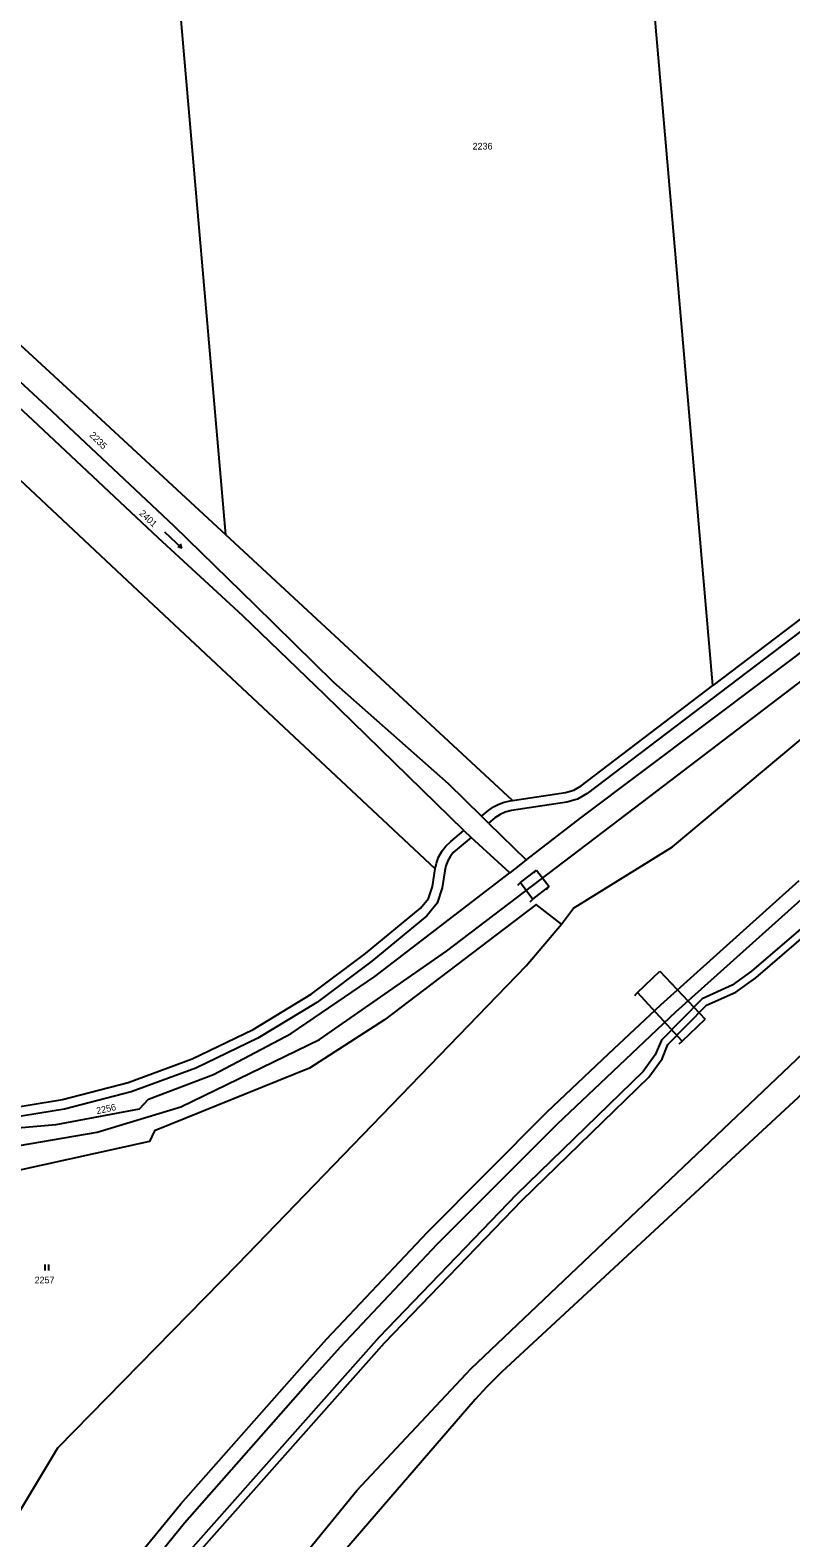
# Model space of a CAD drawing. Extents: x -504988 to -494607, y -1123820 to -1114018.
# Drawn here: x -499040.2 to -498846.7, y -1121962.3 to -1121578.3 of the extents above; entities that cross this region are included whole.
import ezdxf

# ---------------------------------------------------------------- set-up
doc = ezdxf.new("R2010")
doc.units = 0
for name, color, linetype in [('Hranice parcel', 7, 'Continuous'), ('Parcelní čísla', 7, 'Continuous'), ('Poz předměty', 7, 'Continuous'), ('Vnitřní kresba', 7, 'Continuous'), ('Věcná břemena k části', 7, 'Continuous'), ('Značky kultur', 7, 'Continuous')]:
    doc.layers.add(name, color=color, linetype=linetype)

msp = doc.modelspace()

# ---------------------------------------------------------------- linework, layer by layer
at = {"layer": 'Hranice parcel'}
for p, q in [((-498917.52, -1121774.47), (-498990.43, -1121706.85)), ((-498923.58, -1121780.26), (-498925.38, -1121778.5)), ((-498923.58, -1121780.26), (-498914, -1121789.64)), ((-498929.86, -1121782.17), (-498927.99, -1121783.94)), ((-498918.2, -1121792.88), (-498927.99, -1121783.94))]:
    msp.add_line(p, q, dxfattribs=at)
for points in [[(-498866.47, -1121745.24), (-498879.54, -1121594.25), (-498892.61, -1121443.25)], [(-498990.43, -1121706.85), (-499001.1, -1121583.62), (-499011.76, -1121460.39)], [(-498538.01, -1121477.88), (-498569.56, -1121529.32), (-498579.83, -1121544.03), (-498591.77, -1121557.42), (-498605.21, -1121569.3), (-498619.96, -1121579.5), (-498732.29, -1121647.73), (-498740.98, -1121653.33), (-498749.37, -1121659.37), (-498898.52, -1121772.74), (-498900.95, -1121774.14), (-498903.65, -1121774.9), (-498917.72, -1121777.03), (-498919.32, -1121777.43), (-498920.66, -1121778.04), (-498921.96, -1121778.92), (-498923.58, -1121780.26)], [(-498914, -1121789.64), (-498913.86, -1121789.53), (-498900.12, -1121778.95), (-498774.91, -1121684.77), (-498768.24, -1121679.75), (-498738.52, -1121657.4), (-498715.59, -1121643.62), (-498682.52, -1121624.8), (-498650.6, -1121606.88), (-498629.68, -1121595.09), (-498598.09, -1121571.17), (-498579, -1121548.45), (-498555.72, -1121510.08), (-498538.84, -1121481), (-498537.25, -1121478.26)], [(-498905.05, -1121806.02), (-498901.99, -1121801.93), (-498876.77, -1121786.32), (-498775.84, -1121701.77), (-498740.86, -1121675.73), (-498709.59, -1121654.46), (-498671.28, -1121630.46), (-498564.1, -1121580.75), (-498495.09, -1121548.95), (-498498.9, -1121529.72), (-498500.1, -1121523.64), (-498505.78, -1121492.74)], [(-498555.23, -1121501.17), (-498571.7, -1121528.02), (-498581.8, -1121542.48), (-498593.54, -1121555.65), (-498606.75, -1121567.33), (-498621.26, -1121577.37), (-498733.59, -1121645.6), (-498742.39, -1121651.26), (-498750.89, -1121657.38), (-498866.47, -1121745.24)], [(-499000.48, -1122008.5), (-498998.46, -1122000.92), (-498957.1, -1121950.18), (-498928.11, -1121919.18), (-498841.81, -1121837.2), (-498840.75, -1121836.19), (-498837.47, -1121833.23), (-498757.15, -1121760.88), (-498721.23, -1121733.16), (-498721.69, -1121739.51), (-498654.67, -1121691.99), (-498621.86, -1121665.7), (-498610.05, -1121656.24), (-498572.09, -1121630.11), (-498534.03, -1121605.63), (-498489.21, -1121578.24), (-498451.03, -1121555.26), (-498445.93, -1121552.19), (-498412.54, -1121539.26)], [(-499149.08, -1121616.48), (-499136.35, -1121616.98), (-499129.71, -1121616.1), (-499117.81, -1121617.5), (-499096.78, -1121624.2), (-499073.93, -1121639.14), (-499036.06, -1121674.08), (-499003.69, -1121704.58), (-498983.09, -1121724.69), (-498963.04, -1121744.39), (-498933.88, -1121770.18), (-498925.38, -1121778.5)], [(-498929.86, -1121782.17), (-498965.23, -1121747.63), (-498986.15, -1121727.51), (-499007.63, -1121707.59), (-499039.56, -1121677.69), (-499073.7, -1121646), (-499094.22, -1121630.8), (-499111.67, -1121623.38), (-499128.27, -1121620.51), (-499144.04, -1121623.98), (-499151.52, -1121625.62)], [(-498937.2, -1121791.9), (-499014.09, -1121719.86), (-499090.98, -1121647.81), (-499104.22, -1121639.12), (-499120.52, -1121633.88), (-499135.44, -1121634.17), (-499155.01, -1121639.17)], [(-499058, -1121644.5), (-499023.32, -1121676.35), (-498990.43, -1121706.85)], [(-498917.52, -1121774.47), (-498904.02, -1121772.43), (-498901.92, -1121771.84), (-498900.03, -1121770.75), (-498866.47, -1121745.24)], [(-498925.38, -1121778.5), (-498923.55, -1121776.99), (-498922.29, -1121776.09), (-498920.98, -1121775.4), (-498919.57, -1121774.89), (-498918.09, -1121774.56), (-498917.52, -1121774.47)], [(-498927.99, -1121783.94), (-498932.56, -1121787.75), (-498933.39, -1121788.82), (-498933.98, -1121789.86), (-498934.47, -1121791.14), (-498934.74, -1121792.4), (-498935.36, -1121796.74), (-498936.68, -1121800.66), (-498939.32, -1121803.84), (-498953.28, -1121815.39), (-498967.31, -1121825.9), (-498982.28, -1121835), (-498998.06, -1121842.62), (-499014.51, -1121848.67), (-499031.47, -1121853.11), (-499048.77, -1121855.9), (-499066.26, -1121856.99), (-499083.78, -1121856.4), (-499101.15, -1121854.11), (-499118.23, -1121850.16), (-499144.81, -1121842.63)], [(-498937.2, -1121791.9), (-498936.86, -1121790.42), (-498936.29, -1121788.91), (-498935.42, -1121787.36), (-498934.44, -1121786.09), (-498933.22, -1121784.93), (-498929.86, -1121782.17)], [(-499049.05, -1121853.41), (-499031.98, -1121850.67), (-499015.26, -1121846.29), (-498999.04, -1121840.32), (-498983.47, -1121832.8), (-498968.71, -1121823.82), (-498954.87, -1121813.46), (-498940.92, -1121801.91), (-498938.86, -1121799.44), (-498937.83, -1121796.39), (-498937.2, -1121791.9)], [(-498914, -1121789.64), (-498915.79, -1121791.04), (-498918.2, -1121792.88)], [(-499144.81, -1121842.63), (-499143.52, -1121843.53), (-499139.17, -1121845.68), (-499106.35, -1121855.43), (-499080.4, -1121857.12), (-499078.61, -1121857.24), (-499079.46, -1121859.32), (-499067.94, -1121859.99), (-499033.65, -1121857.01), (-499012.44, -1121852.99), (-499010.15, -1121850.53), (-498993.59, -1121844.27), (-498973.79, -1121833.82), (-498952.54, -1121819.34), (-498918.2, -1121792.88)], [(-498905.05, -1121806.02), (-498911.48, -1121801.01), (-498950.02, -1121830.34), (-498969.17, -1121842.68), (-499008.55, -1121858.61), (-499009.88, -1121861.29), (-499044.06, -1121868.88), (-499063.78, -1121870.36), (-499085.95, -1121870.14), (-499097.79, -1121903.09)], [(-499047.42, -1121960.83), (-499045.12, -1121959.32), (-499033.21, -1121939.35), (-498987.34, -1121892.56), (-498914.04, -1121816.6), (-498905.05, -1121806.02)], [(-498831.03, -1121837.41), (-498920.32, -1121920.05), (-498924.06, -1121923.81), (-498926.95, -1121927.01), (-498990.74, -1122000.94), (-498992.65, -1122003.89), (-498993.35, -1122005.71)]]:
    msp.add_lwpolyline(points, dxfattribs=at)
at = {"layer": 'Poz předměty'}
for p, q in [((-498882.52, -1121773.46), (-498836.54, -1121738.36)), ((-498934.31, -1121812.86), (-498882.52, -1121773.46)), ((-498879.73, -1121826.51), (-498844.58, -1121794.87)), ((-498842.5, -1121798.35), (-498876.02, -1121828.36)), ((-498966.61, -1121835.4), (-498934.31, -1121812.86)), ((-498893.03, -1121839.04), (-498879.73, -1121826.51)), ((-498876.02, -1121828.36), (-498893.53, -1121845.07)), ((-499001.85, -1121852.52), (-498966.61, -1121835.4)), ((-498908.68, -1121853.76), (-498893.03, -1121839.04)), ((-498893.53, -1121845.07), (-498906.15, -1121856.88)), ((-499023.19, -1121858.99), (-499001.85, -1121852.52)), ((-498939.11, -1121884.44), (-498908.68, -1121853.76)), ((-498906.15, -1121856.88), (-498936.62, -1121887.44)), ((-499049.55, -1121863.51), (-499023.19, -1121858.99)), ((-498964.76, -1121911.58), (-498939.11, -1121884.44)), ((-498936.62, -1121887.44), (-498961.36, -1121913.74)), ((-498969.06, -1121916.4), (-498964.76, -1121911.58)), ((-498961.36, -1121913.74), (-498968.89, -1121922.11)), ((-499001.91, -1121953.56), (-498969.06, -1121916.4)), ((-498968.89, -1121922.11), (-499000.93, -1121958.53)), ((-499040.01, -1122000.02), (-499001.91, -1121953.56)), ((-499000.93, -1121958.53), (-499038.65, -1122004.77))]:
    msp.add_line(p, q, dxfattribs=at)
at = {"layer": 'Vnitřní kresba'}
for p, q in [((-498915.44, -1121795.39), (-498911.36, -1121792.22)), ((-498912.07, -1121792.93), (-498911.36, -1121792.22)), ((-498911.36, -1121792.22), (-498908.14, -1121796.43)), ((-498916.15, -1121796.1), (-498915.44, -1121795.39)), ((-498915.44, -1121795.39), (-498912.31, -1121799.63)), ((-498912.31, -1121799.63), (-498908.14, -1121796.43)), ((-498908.85, -1121797.14), (-498908.14, -1121796.43)), ((-498913.02, -1121800.34), (-498912.31, -1121799.63)), ((-498885.64, -1121823.42), (-498879.99, -1121817.93)), ((-498880.7, -1121818.64), (-498879.99, -1121817.93)), ((-498879.99, -1121817.93), (-498868.42, -1121830.16)), ((-498886.35, -1121824.13), (-498885.64, -1121823.42)), ((-498874.34, -1121835.77), (-498885.64, -1121823.42)), ((-498874.34, -1121835.77), (-498868.42, -1121830.16)), ((-498869.13, -1121830.87), (-498868.42, -1121830.16)), ((-498875.05, -1121836.48), (-498874.34, -1121835.77))]:
    msp.add_line(p, q, dxfattribs=at)
at = {"layer": 'Věcná břemena k části'}
for points in [[(-498822.7, -1121788.76), (-498856.7, -1121818), (-498861.57, -1121821.53), (-498869.22, -1121825.03), (-498879.6, -1121835.55), (-498881.16, -1121839.27), (-498884.23, -1121843.53), (-498916.43, -1121874.82), (-498951.53, -1121911.22), (-499002.82, -1121969.12)], [(-499001.31, -1121970.43), (-498950.05, -1121912.58), (-498915.02, -1121876.24), (-498882.83, -1121844.96), (-498879.41, -1121840.26), (-498877.97, -1121836.64), (-498868.1, -1121826.64), (-498860.65, -1121823.31), (-498855.53, -1121819.62), (-498821.43, -1121790.3)]]:
    msp.add_lwpolyline(points, dxfattribs=at)
at = {"layer": 'Značky kultur'}
for p, q in [((-499006.01, -1121706.12), (-499001.62, -1121710.21)), ((-499001.62, -1121710.21), (-499002.68, -1121709.91)), ((-499001.62, -1121710.21), (-499001.99, -1121709.18)), ((-499036.44, -1121894.17), (-499036.44, -1121892.67)), ((-499035.44, -1121894.17), (-499035.44, -1121892.67))]:
    msp.add_line(p, q, dxfattribs=at)

# ---------------------------------------------------------------- texts
at = {"layer": 'Parcelní čísla'}
for s, p in [('2236', (-498927.64, -1121608.74)), ('2257', (-499039.09, -1121897.45))]:
    msp.add_text(s, height=1.7, dxfattribs=at).set_placement(p)
for s, rotation, p in [('2235', 315, (-499025.26, -1121681.63)), ('2401', 317, (-499012.59, -1121701.59)), ('2256', 12, (-499023.2, -1121854.38))]:
    msp.add_text(s, height=1.7, rotation=rotation, dxfattribs=at).set_placement(p)

doc.saveas('drawing.dxf')
